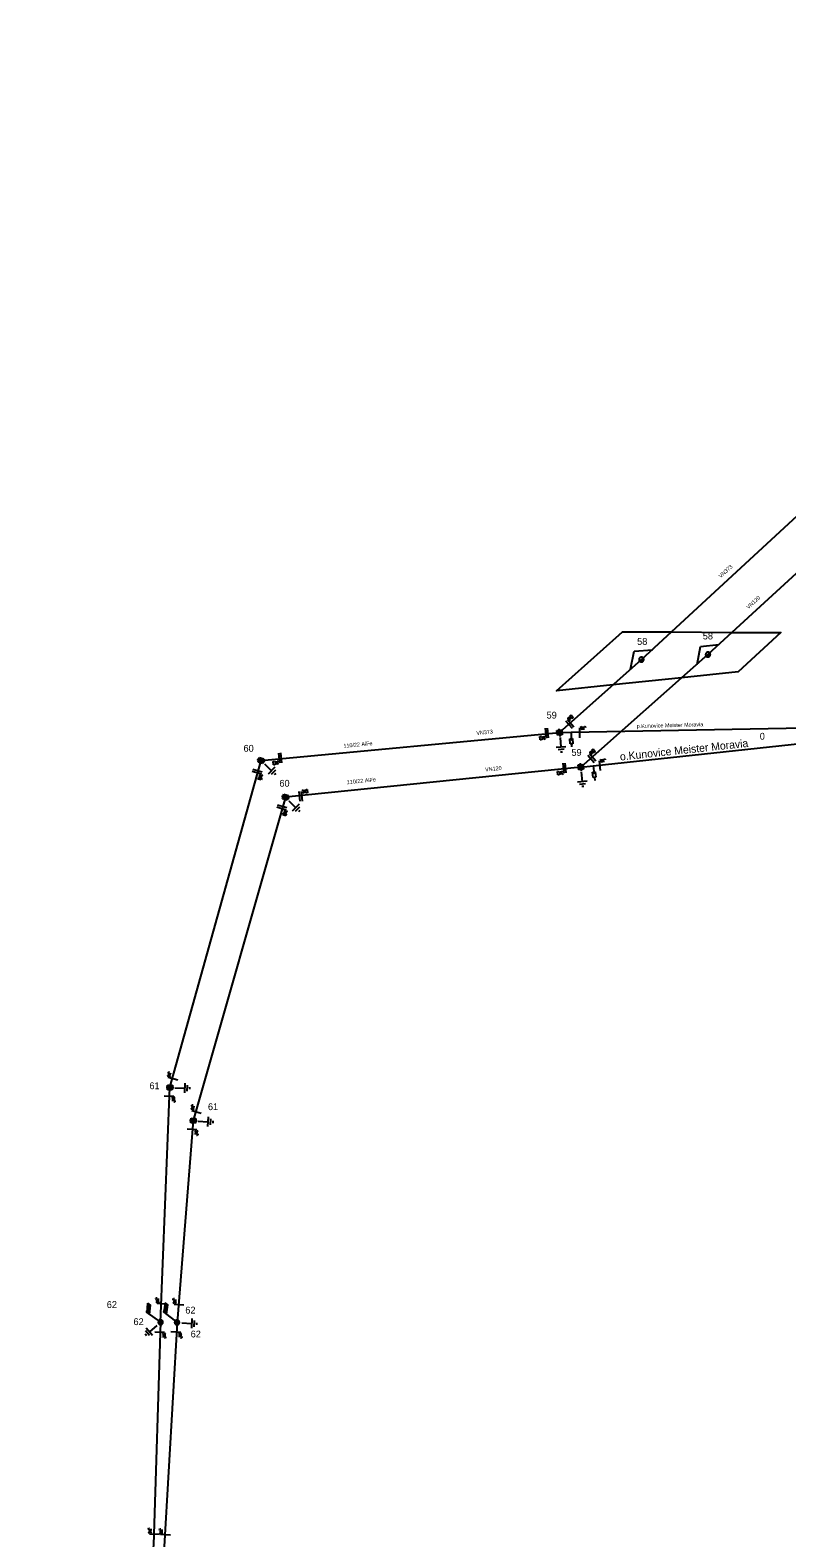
# Model space of a CAD drawing. Extents: x -540879 to -537255, y -1184046 to -1180016.
# Drawn here: x -540045.7 to -539852.2, y -1183409.6 to -1183024 of the extents above; entities that cross this region are included whole.
import ezdxf

# ---------------------------------------------------------------- set-up
doc = ezdxf.new("R2010")
doc.units = 0
for name, color, linetype in [('Default', 7, 'Continuous'), ('Vrstva 1', 7, 'Continuous'), ('Vrstva 11', 7, 'Continuous'), ('Vrstva 12', 7, 'Continuous'), ('Vrstva 13', 7, 'Continuous'), ('Vrstva 14', 7, 'Continuous'), ('Vrstva 15', 7, 'Continuous'), ('Vrstva 16', 7, 'Continuous'), ('Vrstva 18', 7, 'Continuous'), ('Vrstva 2', 7, 'Continuous'), ('Vrstva 3', 7, 'Continuous'), ('Vrstva 35', 7, 'Continuous'), ('Vrstva 4', 7, 'Continuous'), ('Vrstva 52', 7, 'Continuous'), ('Vrstva 54', 7, 'Continuous'), ('Vrstva 59', 7, 'Continuous')]:
    doc.layers.add(name, color=color, linetype=linetype)

# ---------------------------------------------------------------- blocks, each defined once
blk = doc.blocks.new('VN850')
at = {"layer": 'Vrstva 15'}
for points in [[(-0.56, 1.43), (-0.56, -1.07)], [(-0.01, 1.43), (-0.01, -1.07)], [(-2.09, -0.54), (-1.78, -0.54)], [(-2.09, -1.41), (-2.09, -0.54)], [(-1.78, -1.41), (-2.09, -1.41)], [(-1.78, -0.54), (-1.66, -0.6)], [(-1.67, -1.35), (-1.78, -1.41)], [(-1.59, -1.2), (-1.67, -1.35)], [(-1.66, -0.6), (-1.59, -0.75)], [(-1.59, -0.75), (-1.55, -0.96)], [(-1.55, -0.96), (-1.59, -1.2)], [(-1.26, -0.54), (-1.26, -1.41)], [(-0.85, -0.54), (-1.26, -1.09)], [(-1.13, -0.92), (-0.77, -1.41)]]:
    blk.add_lwpolyline(points, dxfattribs=at)
blk = doc.blocks.new('VN840')
at = {"layer": 'Vrstva 15'}
for points in [[(-0.01, 1.41), (-0.01, -1.09)], [(-1.51, -1.24), (-1.51, -1.15)], [(-1.48, -1.35), (-1.51, -1.24)], [(-1.33, -1.42), (-1.48, -1.35)], [(-1.27, -1.42), (-1.33, -1.42)], [(-1.13, -1.35), (-1.27, -1.42)], [(-1.09, -1.24), (-1.13, -1.35)], [(-1.09, -0.59), (-1.09, -1.24)], [(-0.68, -0.59), (-0.68, -1.42)], [(-0.68, -1.11), (-0.27, -0.59)], [(-0.54, -0.94), (-0.2, -1.42)]]:
    blk.add_lwpolyline(points, dxfattribs=at)
blk = doc.blocks.new('VN860')
at = {"layer": 'Vrstva 15'}
for points in [[(-3.74, 0), (0.01, 2.82)], [(0.01, 2.82), (3.76, 0)]]:
    blk.add_lwpolyline(points, dxfattribs=at)
blk = doc.blocks.new('VN440')
at = {"layer": 'Vrstva 2'}
for points in [[(1.22, 0), (1.21, 0.13), (1.19, 0.25), (1.16, 0.38), (1.11, 0.5), (1.05, 0.61), (0.98, 0.72), (0.9, 0.82), (0.81, 0.91), (0.71, 0.99), (0.6, 1.06), (0.49, 1.12), (0.37, 1.16), (0.25, 1.2), (0.12, 1.22), (-0.01, 1.22), (-0.14, 1.22), (-0.26, 1.2), (-0.39, 1.16), (-0.51, 1.12), (-0.62, 1.06), (-0.73, 0.99), (-0.83, 0.91), (-0.92, 0.82), (-1, 0.72), (-1.07, 0.61), (-1.13, 0.5), (-1.18, 0.38), (-1.21, 0.25), (-1.23, 0.13), (-1.24, 0), (-1.23, -0.13), (-1.21, -0.26), (-1.18, -0.38), (-1.13, -0.5), (-1.07, -0.62), (-1, -0.73), (-0.92, -0.83), (-0.83, -0.92), (-0.73, -1), (-0.62, -1.07), (-0.51, -1.13), (-0.39, -1.17), (-0.26, -1.2), (-0.14, -1.23), (-0.01, -1.23), (0.12, -1.23), (0.25, -1.2), (0.37, -1.17), (0.49, -1.13), (0.6, -1.07), (0.71, -1), (0.81, -0.92), (0.9, -0.83), (0.98, -0.73), (1.05, -0.62), (1.11, -0.5), (1.16, -0.38), (1.19, -0.26), (1.21, -0.13), (1.22, 0)], [(-1.24, 0), (1.22, 0)], [(-1.18, -0.34), (1.1, -0.34)], [(-1.01, -0.63), (0.97, -0.63)], [(-0.74, -0.92), (0.68, -0.92)]]:
    blk.add_lwpolyline(points, dxfattribs=at)
blk = doc.blocks.new('VN820')
at = {"layer": 'Vrstva 13'}
for points in [[(0, 0), (0, -2.1)], [(-0.32, -1.63), (0.34, -1.63)], [(-0.32, -2.95), (-0.32, -1.63)], [(0.34, -2.95), (-0.32, -2.95)], [(0, -2.1), (-0.12, -1.86)], [(0, -2.1), (0.12, -1.86)], [(0, -2.95), (0, -3.75)], [(0.34, -1.63), (0.34, -2.95)]]:
    blk.add_lwpolyline(points, dxfattribs=at)
blk = doc.blocks.new('VN810')
at = {"layer": 'Vrstva 14'}
for points in [[(1.25, -3.75), (-1.25, -3.75)], [(0, -1.25), (0, -3.75)], [(0.77, -4.37), (-0.8, -4.37)], [(0, -5), (-0.25, -5)], [(0.27, -5), (0, -5)]]:
    blk.add_lwpolyline(points, dxfattribs=at)
blk = doc.blocks.new('VN001')
at = {"layer": 'Default'}
for p, q in [((1.73, 3.03), (4.14, 3.03)), ((1.76, 3.08), (4.17, 3.08)), ((1.79, 3.13), (4.2, 3.13)), ((1.82, 3.18), (4.23, 3.18)), ((1.85, 3.23), (4.26, 3.23)), ((1.87, 3.28), (4.29, 3.28)), ((1.9, 3.33), (4.32, 3.33)), ((1.93, 3.38), (4.35, 3.38)), ((1.96, 3.43), (4.37, 3.43)), ((1.99, 3.48), (4.4, 3.48)), ((2.02, 3.53), (4.43, 3.53)), ((2.05, 3.58), (4.46, 3.58)), ((2.07, 3.63), (4.49, 3.63)), ((2.1, 3.68), (4.52, 3.68)), ((2.13, 3.73), (2.54, 3.73))]:
    blk.add_line(p, q, dxfattribs=at)
blk.add_lwpolyline([(2.13, 3.73), (0, 0)], dxfattribs=at)
blk.add_lwpolyline([(4.55, 3.73), (2.13, 3.73), (1.7, 2.98), (4.12, 2.99)], close=True, dxfattribs=at)
blk = doc.blocks.new('VN470')
at = {"layer": 'Vrstva 2'}
for points in [[(-1.23, 1.22), (1.23, 1.22)], [(-1.23, -1.23), (-1.23, 1.22)], [(-0.92, 0.9), (0.92, 0.9)], [(-0.92, -0.95), (-0.92, 0.9)], [(-0.61, 0.61), (0.61, 0.61)], [(-0.61, -0.62), (-0.61, 0.61)], [(-0.31, -0.27), (-0.31, 0.34)], [(-0.31, 0.34), (0.31, 0.34)], [(0, 1.22), (0, 1.97)], [(0.31, 0.34), (0.31, -0.27)], [(0.61, 0.61), (0.61, -0.62)], [(0.92, 0.9), (0.92, -0.95)], [(1.23, 1.22), (1.23, -1.23)], [(1.23, -1.23), (-1.23, -1.23)], [(0.92, -0.95), (-0.92, -0.95)], [(0.61, -0.62), (-0.61, -0.62)], [(0.31, -0.27), (-0.31, -0.27)], [(0, -1.23), (0, -1.98)]]:
    blk.add_lwpolyline(points, dxfattribs=at)

msp = doc.modelspace()

# ---------------------------------------------------------------- linework, layer by layer
at = {"layer": 'Vrstva 1'}
for points in [[(-538750.53, -1181681.2), (-538749.33, -1181712.71), (-538744.97, -1181817.24), (-538743.58, -1181895.5), (-538773.54, -1181977.77), (-538805.22, -1182060.54), (-538837.47, -1182145.44), (-538866.82, -1182220.96), (-538895.79, -1182296.47), (-538969.65, -1182362.9), (-539051.89, -1182437.77), (-539124.04, -1182501.28), (-539198.82, -1182569.8), (-539277.47, -1182640.72), (-539357.09, -1182713.05), (-539436.34, -1182785.46), (-539516.79, -1182858.47), (-539596.04, -1182930.58), (-539682.18, -1183009.05), (-539746.81, -1183068.3), (-539812.77, -1183128.96), (-539872.34, -1183183.66), (-539904.86, -1183212.44)], [(-539910.31, -1183203.61), (-539889.36, -1183184.93), (-539819.58, -1183120.53), (-539757.27, -1183063.3), (-539687.65, -1182999.5), (-539602.47, -1182922.15), (-539522.85, -1182849.96), (-539443.45, -1182777.85), (-539363.3, -1182704.92), (-539283.21, -1182632.72)], [(-540012.36, -1183354.43), (-540009.96, -1183294.39), (-539986.67, -1183210.74), (-539910.31, -1183203.61)], [(-539904.86, -1183212.44), (-539980.4, -1183220.14), (-540003.99, -1183302.87), (-540008.15, -1183354.48)], [(-540012.36, -1183354.43), (-540014.17, -1183411.34), (-540028.85, -1183530.04), (-540045.72, -1183647.03)], [(-540008.15, -1183354.48), (-540011.44, -1183411.77), (-540026.2, -1183530.3), (-540043.23, -1183647.3)]]:
    msp.add_lwpolyline(points, dxfattribs=at)
at = {"layer": 'Vrstva 35'}
msp.add_lwpolyline([(-539881.74, -1183177.89), (-539866.16, -1183177.99), (-539853.68, -1183178.06), (-539864.63, -1183188.12), (-539879.07, -1183189.62), (-539896.66, -1183191.44), (-539911.11, -1183192.93), (-539895.07, -1183178.63), (-539894.19, -1183177.82)], close=True, dxfattribs=at)
at = {"layer": 'Vrstva 4'}
msp.add_lwpolyline([(-539910.31, -1183203.61), (-539907.36, -1183203.55), (-539843.22, -1183202.3)], dxfattribs=at)
at = {"layer": 'Vrstva 52'}
msp.add_lwpolyline([(-539904.86, -1183212.44), (-539901.69, -1183212.1), (-539845.55, -1183206.08)], dxfattribs=at)

# ---------------------------------------------------------------- block references
at = {"layer": 'Vrstva 11'}
for p, rotation in [((-540012.36, -1183354.43), 84.61605272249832), ((-540008.15, -1183354.48), 81.48321104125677)]:
    msp.add_blockref('VN001', p, dxfattribs=dict(at, rotation=rotation))
at = {"layer": 'Vrstva 13'}
for name, p, xscale, yscale, rotation in [('VN440', (-539889.36, -1183184.93), 0.5, 0.5, 41.722772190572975), ('VN440', (-539872.34, -1183183.66), 0.5, 0.5, 41.44218061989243), ('VN470', (-539910.31, -1183203.61), 0.49999999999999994, 0.5000000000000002, 5.629222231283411), ('VN470', (-539986.67, -1183210.74), 0.5, 0.5, 74.09066667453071), ('VN470', (-539904.86, -1183212.45), 0.5000000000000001, 0.5, 5.814858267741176), ('VN470', (-539980.4, -1183220.14), 0.49999999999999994, 0.5000000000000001, 74.007597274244), ('VN470', (-540009.96, -1183294.39), 0.49999999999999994, 0.49999999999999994, 87.9287444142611), ('VN470', (-540003.99, -1183302.87), 0.5, 0.49999999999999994, 85.94546111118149), ('VN440', (-540012.36, -1183354.43), 0.5, 0.5, 87.76985553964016), ('VN440', (-540008.15, -1183354.48), 0.5, 0.5000000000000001, 86.1933361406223)]:
    msp.add_blockref(name, p, dxfattribs=dict(at, xscale=xscale, yscale=yscale, rotation=rotation))
at = {"layer": 'Vrstva 15'}
for p, rotation in [((-539910.31, -1183203.61), 5.629222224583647), ((-539986.67, -1183210.74), 45.70227779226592), ((-539904.86, -1183212.44), 5.814858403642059), ((-539980.4, -1183220.14), 44.25360546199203), ((-540009.96, -1183294.39), 87.92874448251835), ((-540003.99, -1183302.87), 85.94546111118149), ((-540012.36, -1183354.43), -49.45121385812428), ((-540008.15, -1183354.48), 86.1933361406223)]:
    msp.add_blockref('VN810', p, dxfattribs=dict(at, rotation=rotation))
at = {"layer": 'Vrstva 16'}
for p, rotation in [((-539907.36, -1183203.55), 1.5765195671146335), ((-539901.69, -1183212.1), 5.958369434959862)]:
    msp.add_blockref('VN820', p, dxfattribs=dict(at, rotation=rotation))
at = {"layer": 'Vrstva 18'}
for name, p, rotation in [('VN860', (-539889.36, -1183184.93), 41.721525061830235), ('VN860', (-539872.34, -1183183.66), 42.35320559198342), ('VN850', (-539907.99, -1183201.54), -138.27847493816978), ('VN850', (-539913.31, -1183203.89), 5.337066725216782), ('VN840', (-539905.14, -1183203.51), -178.88356102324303), ('VN850', (-539981.52, -1183210.26), 5.337066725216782), ('VN850', (-539902.38, -1183210.25), -138.5581694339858), ('VN850', (-539987.4, -1183213.34), 74.56577217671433), ('VN850', (-539908.79, -1183212.84), 5.815036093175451), ('VN840', (-539899.98, -1183211.92), -173.87483891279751), ('VN850', (-539976.77, -1183219.77), -174.18496391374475), ('VN850', (-539981.07, -1183222.5), 74.00756939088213), ('VN840', (-540009.34, -1183292.17), -105.43422778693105), ('VN840', (-540010.05, -1183296.55), 87.92942494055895), ('VN840', (-540003.35, -1183300.63), -105.99243060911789), ('VN840', (-540004.17, -1183305.05), 85.94597781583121), ('VN840', (-540012.17, -1183349.72), -92.25707495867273), ('VN840', (-540007.79, -1183349.97), -94.18905552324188), ('VN840', (-540012.45, -1183356.96), 87.95846395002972), ('VN840', (-540008.29, -1183356.89), 86.30751940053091), ('VN840', (-540014.08, -1183408.65), -91.81863880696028), ('VN840', (-540011.27, -1183408.81), -93.28678055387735)]:
    msp.add_blockref(name, p, dxfattribs=dict(at, rotation=rotation))

# ---------------------------------------------------------------- texts
at = {"layer": 'Vrstva 12'}
for s, p in [('0', (-539859.09, -1183205.43)), ('62', (-540026.12, -1183350.78)), ('62', (-540006.03, -1183352.21))]:
    msp.add_text(s, height=1.75, dxfattribs=at).set_placement(p)
at = {"layer": 'Vrstva 14'}
for s, p in [('58', (-539873.66, -1183179.79)), ('58', (-539890.46, -1183181.18)), ('59', (-539913.62, -1183200.03)), ('60', (-539991.14, -1183208.51)), ('59', (-539907.26, -1183209.57)), ('60', (-539981.96, -1183217.46)), ('61', (-540015.21, -1183294.82)), ('61', (-540000.24, -1183300.18)), ('62', (-540019.29, -1183355.16)), ('62', (-540004.66, -1183358.32))]:
    msp.add_text(s, height=1.75, dxfattribs=at).set_placement(p)
at = {"layer": 'Vrstva 2'}
for rotation, p in [(5.337, (-539965.53, -1183207.52)), (5.815, (-539964.66, -1183216.84))]:
    msp.add_text('110/22 AlFe', height=1, rotation=rotation, dxfattribs=at).set_placement(p)
at = {"layer": 'Vrstva 3'}
for s, rotation, p in [('VN373', 42.704, (-539869.05, -1183164.16)), ('VN120', 42.559, (-539861.97, -1183172.1)), ('VN373', 5.337, (-539931.54, -1183204.24)), ('VN120', 5.815, (-539929.29, -1183213.57))]:
    msp.add_text(s, height=1, rotation=rotation, dxfattribs=at).set_placement(p)
at = {"layer": 'Vrstva 54'}
msp.add_text('o.Kunovice Meister Moravia', height=2, rotation=6.125, dxfattribs=at).set_placement((-539894.76, -1183210.78))
at = {"layer": 'Vrstva 59'}
msp.add_text('p.Kunovice Meister Moravia', height=1, rotation=1.577, dxfattribs=at).set_placement((-539890.55, -1183202.47))

doc.saveas('drawing.dxf')
